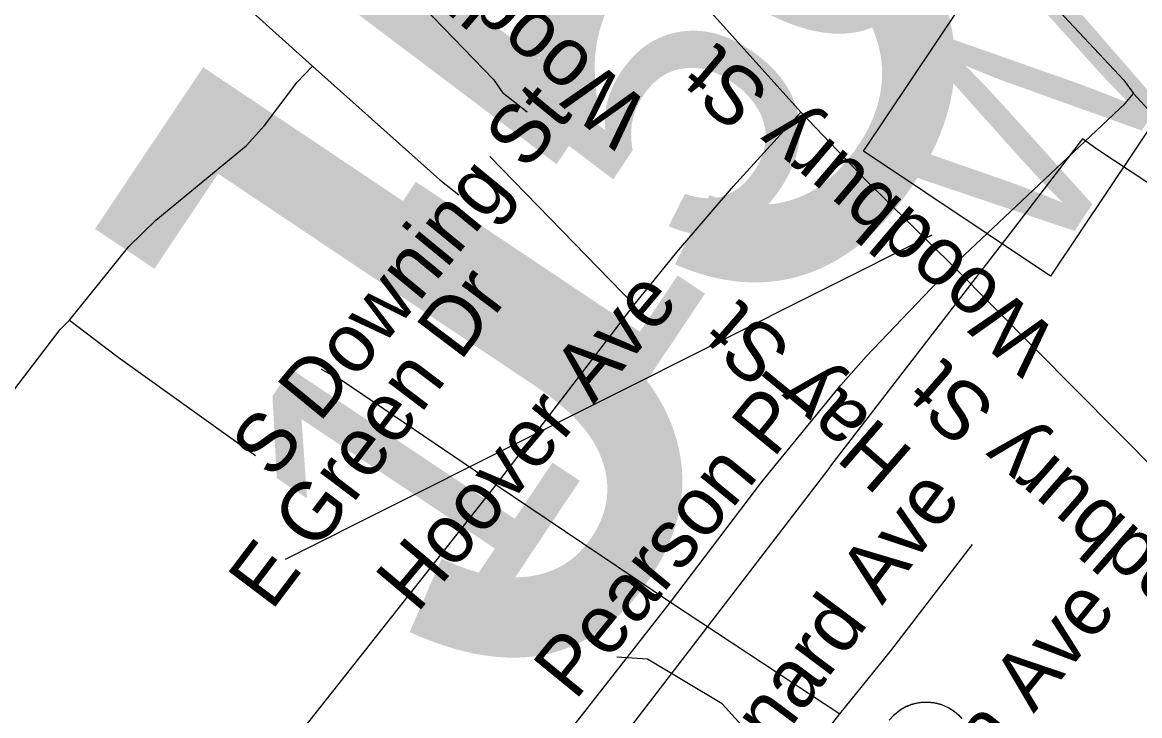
# Model space of a CAD drawing. Extents: x 1716282 to 1717158, y 799307 to 801078.
# Drawn here: x 1716807.84 to 1716834.17, y 800768.71 to 800785.04 of the extents above; entities that cross this region are included whole.
import ezdxf

# ---------------------------------------------------------------- set-up
doc = ezdxf.new("R2010")
doc.units = 0
for name, color, linetype in [('Exist Boundary Political City Limit New', 7, 'Continuous'), ('Exist Hydrographic Misc Water Feature', 7, 'Continuous'), ('Exist Road Non-System Structure Non-Sys Other Number Label', 7, 'Continuous'), ('Exist Road Non-System Type 51', 7, 'Continuous'), ('Exist Road Non-System Type 51 Label', 7, 'Continuous'), ('Exist Road Secondary Structure NCDOT Private Pedestrian Number Label', 7, 'Continuous'), ('Exist Road Secondary Type 51 Label', 7, 'Continuous'), ('Map Preparation Boundary City Limit Buffer Line', 7, 'Continuous'), ('Old_Level_1', 7, 'Continuous')]:
    doc.layers.add(name, color=color, linetype=linetype)

msp = doc.modelspace()

# ---------------------------------------------------------------- linework, layer by layer
at = {"layer": 'Exist Boundary Political City Limit New'}
for points in [[(1716834.778, 800780.982), (1716833.185, 800782.032), (1716832.823, 800782.29), (1716831.114, 800780.071), (1716826.885, 800774.592), (1716826.841, 800774.53), (1716814.586, 800758.566), (1716818.37, 800755.771)], [(1716828.268, 800768.606), (1716828.39, 800768.736), (1716828.479, 800768.81), (1716828.571, 800768.874), (1716828.676, 800768.928), (1716828.801, 800768.978), (1716828.857, 800768.993), (1716828.911, 800769.006), (1716829.026, 800769.024), (1716829.121, 800769.029), (1716829.217, 800769.027), (1716829.311, 800769.016), (1716829.385, 800768.999), (1716829.496, 800768.971), (1716829.515, 800768.962), (1716829.569, 800768.942), (1716829.67, 800768.89), (1716829.794, 800768.814), (1716829.908, 800768.717), (1716829.977, 800768.636)], [(1716828.364, 800768.708), (1716828.379, 800768.724), (1716828.39, 800768.736), (1716828.405, 800768.749), (1716828.421, 800768.761), (1716828.434, 800768.772), (1716828.445, 800768.781), (1716828.458, 800768.792), (1716828.479, 800768.81), (1716828.497, 800768.822), (1716828.512, 800768.831), (1716828.525, 800768.842), (1716828.544, 800768.852), (1716828.56, 800768.865), (1716828.575, 800768.874), (1716828.592, 800768.883), (1716828.609, 800768.891), (1716828.624, 800768.9), (1716828.643, 800768.91), (1716828.66, 800768.919), (1716828.676, 800768.928), (1716828.694, 800768.935), (1716828.712, 800768.943), (1716828.727, 800768.949), (1716828.746, 800768.956), (1716828.765, 800768.963), (1716828.783, 800768.97), (1716828.801, 800768.978), (1716828.82, 800768.982), (1716828.838, 800768.986), (1716828.857, 800768.993), (1716828.876, 800768.997), (1716828.893, 800769.001), (1716828.911, 800769.006), (1716828.931, 800769.009), (1716828.949, 800769.013), (1716828.969, 800769.016), (1716828.987, 800769.017), (1716829.006, 800769.021), (1716829.026, 800769.024), (1716829.045, 800769.024), (1716829.062, 800769.026), (1716829.082, 800769.029), (1716829.102, 800769.029), (1716829.121, 800769.029), (1716829.14, 800769.029), (1716829.159, 800769.029), (1716829.177, 800769.027), (1716829.197, 800769.027), (1716829.217, 800769.027), (1716829.235, 800769.025), (1716829.254, 800769.022), (1716829.274, 800769.022), (1716829.293, 800769.019), (1716829.311, 800769.016), (1716829.33, 800769.01), (1716829.349, 800769.007), (1716829.367, 800769.005), (1716829.385, 800768.999), (1716829.405, 800768.996), (1716829.423, 800768.99), (1716829.442, 800768.987), (1716829.461, 800768.981), (1716829.479, 800768.976), (1716829.496, 800768.971), (1716829.515, 800768.962), (1716829.532, 800768.956), (1716829.55, 800768.948), (1716829.569, 800768.942), (1716829.586, 800768.934), (1716829.602, 800768.926), (1716829.621, 800768.917), (1716829.637, 800768.909), (1716829.654, 800768.898), (1716829.67, 800768.89), (1716829.688, 800768.881), (1716829.703, 800768.871), (1716829.72, 800768.86), (1716829.735, 800768.85), (1716829.747, 800768.842), (1716829.766, 800768.829), (1716829.783, 800768.818), (1716829.799, 800768.807), (1716829.815, 800768.797), (1716829.829, 800768.784), (1716829.843, 800768.771), (1716829.859, 800768.76), (1716829.872, 800768.745), (1716829.885, 800768.733), (1716829.901, 800768.72), (1716829.914, 800768.707)]]:
    msp.add_lwpolyline(points, dxfattribs=at)
at = {"layer": 'Exist Hydrographic Misc Water Feature'}
msp.add_lwpolyline([(1716876.042, 800751.14), (1716872.76, 800752.217), (1716871.349, 800752.22), (1716870.316, 800751.909), (1716868.528, 800750.75), (1716862.768, 800748.302), (1716861.859, 800748.263), (1716861.14, 800748.508), (1716860.381, 800748.958), (1716858.551, 800750.182), (1716851.597, 800754.307), (1716846.485, 800758.817), (1716843.528, 800759.819), (1716840.189, 800759.612), (1716836.246, 800760.699), (1716833.061, 800762.288), (1716827.152, 800765.878), (1716824.331, 800768.986), (1716822.573, 800770.041), (1716821.851, 800770.088)], dxfattribs=at)
at = {"layer": 'Exist Road Non-System Type 51'}
for p, q in [((1716811.841, 800786.567), (1716814.673, 800784.006)), ((1716818.852, 800781.874), (1716822.257, 800778.38)), ((1716819.003, 800774.143), (1716822.257, 800778.38)), ((1716813.112, 800766.697), (1716819.003, 800774.143)), ((1716819.003, 800774.143), (1716823.114, 800771.382)), ((1716823.114, 800771.382), (1716827.101, 800768.752)), ((1716822.589, 800762.941), (1716827.101, 800768.752))]:
    msp.add_line(p, q, dxfattribs=at)
for points in [[(1716826.682, 800791.347), (1716829.88, 800787.93), (1716831.564, 800786.059), (1716833.795, 800783.674), (1716834.023, 800783.364)], [(1716814.761, 800790.409), (1716817.533, 800787.648), (1716817.59, 800787.48), (1716817.492, 800787.306), (1716816.621, 800786.34), (1716816.641, 800786.144), (1716816.81, 800785.897), (1716818.939, 800783.694), (1716819.152, 800783.381), (1716819.737, 800782.93)], [(1716822.865, 800786.713), (1716823.16, 800786.286), (1716826.183, 800782.924)], [(1716808.954, 800778.025), (1716810.353, 800779.754), (1716810.988, 800780.374), (1716813.123, 800782.14), (1716813.542, 800782.608), (1716814.318, 800783.631), (1716814.673, 800784.006)], [(1716814.673, 800784.006), (1716817.68, 800781.326), (1716818.122, 800780.975)], [(1716829.764, 800779.305), (1716833.828, 800783.128), (1716834.023, 800783.364)], [(1716834.023, 800783.364), (1716836.641, 800780.495), (1716838.48, 800778.577), (1716839.826, 800777.269), (1716839.906, 800777.219), (1716840.012, 800777.218), (1716840.149, 800777.244)], [(1716822.257, 800778.38), (1716823.262, 800779.622), (1716824.595, 800781.182), (1716826.183, 800782.924)], [(1716826.183, 800782.924), (1716827.73, 800781.304), (1716829.764, 800779.305)], [(1716823.114, 800771.382), (1716825.268, 800774.218), (1716827.128, 800776.49), (1716827.719, 800777.167), (1716829.764, 800779.305)], [(1716829.764, 800779.305), (1716837.522, 800771.48), (1716839.86, 800769.287), (1716840.28, 800769.113)], [(1716802.863, 800774.789), (1716804.884, 800773.225), (1716805.066, 800773.14), (1716805.167, 800773.147), (1716808.732, 800777.803), (1716808.954, 800778.025)], [(1716808.954, 800778.025), (1716810.099, 800777.148), (1716813.331, 800774.834)], [(1716814.879, 800776.867), (1716815.377, 800776.599), (1716819.003, 800774.143)], [(1716827.101, 800768.752), (1716828.301, 800770.237), (1716830.225, 800772.742)], [(1716818.636, 800765.807), (1716819.345, 800766.565), (1716823.114, 800771.382)]]:
    msp.add_lwpolyline(points, dxfattribs=at)
at = {"layer": 'Exist Road Secondary Structure NCDOT Private Pedestrian Number Label'}
msp.add_line((1716814.041, 800772.394), (1716829.279, 800780.034), dxfattribs=at)
msp.add_lwpolyline([(1716827.663, 800782.002), (1716838.952, 800798.867), (1716843.353, 800795.921), (1716832.065, 800779.056)], close=True, dxfattribs=at)
at = {"layer": 'Map Preparation Boundary City Limit Buffer Line'}
for points in [[(1716834.778, 800780.982), (1716833.185, 800782.032), (1716832.823, 800782.29), (1716831.114, 800780.071), (1716826.885, 800774.592), (1716826.841, 800774.53), (1716814.586, 800758.566), (1716818.37, 800755.771)], [(1716828.268, 800768.606), (1716828.39, 800768.736), (1716828.479, 800768.81), (1716828.571, 800768.874), (1716828.676, 800768.928), (1716828.801, 800768.978), (1716828.857, 800768.993), (1716828.911, 800769.006), (1716829.026, 800769.024), (1716829.121, 800769.029), (1716829.217, 800769.027), (1716829.311, 800769.016), (1716829.385, 800768.999), (1716829.496, 800768.971), (1716829.515, 800768.962), (1716829.569, 800768.942), (1716829.67, 800768.89), (1716829.794, 800768.814), (1716829.908, 800768.717), (1716829.977, 800768.636)], [(1716828.364, 800768.708), (1716828.379, 800768.724), (1716828.39, 800768.736), (1716828.405, 800768.749), (1716828.421, 800768.761), (1716828.434, 800768.772), (1716828.445, 800768.781), (1716828.458, 800768.792), (1716828.479, 800768.81), (1716828.497, 800768.822), (1716828.512, 800768.831), (1716828.525, 800768.842), (1716828.544, 800768.852), (1716828.56, 800768.865), (1716828.575, 800768.874), (1716828.592, 800768.883), (1716828.609, 800768.891), (1716828.624, 800768.9), (1716828.643, 800768.91), (1716828.66, 800768.919), (1716828.676, 800768.928), (1716828.694, 800768.935), (1716828.712, 800768.943), (1716828.727, 800768.949), (1716828.746, 800768.956), (1716828.765, 800768.963), (1716828.783, 800768.97), (1716828.801, 800768.978), (1716828.82, 800768.982), (1716828.838, 800768.986), (1716828.857, 800768.993), (1716828.876, 800768.997), (1716828.893, 800769.001), (1716828.911, 800769.006), (1716828.931, 800769.009), (1716828.949, 800769.013), (1716828.969, 800769.016), (1716828.987, 800769.017), (1716829.006, 800769.021), (1716829.026, 800769.024), (1716829.045, 800769.024), (1716829.062, 800769.026), (1716829.082, 800769.029), (1716829.102, 800769.029), (1716829.121, 800769.029), (1716829.14, 800769.029), (1716829.159, 800769.029), (1716829.177, 800769.027), (1716829.197, 800769.027), (1716829.217, 800769.027), (1716829.235, 800769.025), (1716829.254, 800769.022), (1716829.274, 800769.022), (1716829.293, 800769.019), (1716829.311, 800769.016), (1716829.33, 800769.01), (1716829.349, 800769.007), (1716829.367, 800769.005), (1716829.385, 800768.999), (1716829.405, 800768.996), (1716829.423, 800768.99), (1716829.442, 800768.987), (1716829.461, 800768.981), (1716829.479, 800768.976), (1716829.496, 800768.971), (1716829.515, 800768.962), (1716829.532, 800768.956), (1716829.55, 800768.948), (1716829.569, 800768.942), (1716829.586, 800768.934), (1716829.602, 800768.926), (1716829.621, 800768.917), (1716829.637, 800768.909), (1716829.654, 800768.898), (1716829.67, 800768.89), (1716829.688, 800768.881), (1716829.703, 800768.871), (1716829.72, 800768.86), (1716829.735, 800768.85), (1716829.747, 800768.842), (1716829.766, 800768.829), (1716829.783, 800768.818), (1716829.799, 800768.807), (1716829.815, 800768.797), (1716829.829, 800768.784), (1716829.843, 800768.771), (1716829.859, 800768.76), (1716829.872, 800768.745), (1716829.885, 800768.733), (1716829.901, 800768.72), (1716829.914, 800768.707)]]:
    msp.add_lwpolyline(points, dxfattribs=at)

# ---------------------------------------------------------------- texts
at = {"layer": 'Exist Road Non-System Structure Non-Sys Other Number Label'}
msp.add_text('J571', height=15.223, rotation=56.2051, dxfattribs=at).set_placement((1716819.931, 800768.309))
at = {"layer": 'Exist Road Non-System Type 51 Label'}
for s, rotation, p in [('Woodbury St', 139.7268, (1716822.694, 800783.041)), ('Woodbury St', 139.6269, (1716832.306, 800777.673)), ('S Downing St', 50.585, (1716813.732, 800774.239)), ('Hoover Ave', 49.8338, (1716817.136, 800771.096)), ('Hay St', 138.9723, (1716828.888, 800774.905)), ('Woodbury St', 138.7378, (1716837.536, 800770.131)), ('Pearson Pl', 50.7236, (1716820.862, 800769.04)), ('Leonard Ave', 53.1772, (1716823.739, 800765.468)), ('Olga Ave', 50.9904, (1716828.895, 800765.324)), ('Furlough Ave', 56.2051, (1716831.336, 800761.065))]:
    msp.add_text(s, height=1.3775, rotation=rotation, dxfattribs=at).set_placement(p)
at = {"layer": 'Exist Road Secondary Structure NCDOT Private Pedestrian Number Label'}
msp.add_text('W509', height=5.075, rotation=56.2051, dxfattribs=at).set_placement((1716831.852, 800778.956))
at = {"layer": 'Exist Road Secondary Type 51 Label'}
msp.add_text('E Green Dr', height=1.3775, rotation=52.9013, dxfattribs=at).set_placement((1716813.711, 800771.153))
at = {"layer": 'Old_Level_1'}
msp.add_text('1156', height=7.128, rotation=56.2051, dxfattribs=at).set_placement((1716818.285, 800770.221))

doc.saveas('drawing.dxf')
